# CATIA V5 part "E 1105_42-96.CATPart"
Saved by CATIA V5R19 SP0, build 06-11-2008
Definition: E 1105_42-96
Nomenclature: E 1105_42-96
Description: PART--DESC
Material "Brass": density 8216 kg/m3, Young's modulus 1.31e+11 Pa, Poisson ratio 0.35, thermal expansion 1.67e-05 1/K
Bounding box of the stored display mesh (mm): x 249.5 to 308.5, y 199.51 to 258.49, z -172 to -66
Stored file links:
  G:\UTB\Kombinované\Bakalářská práce\Catia\FORMA\E 1105_42-96.CATPart
  D:\Aplikace\CATIA\Nová složka\win_b64\startup\materials\Catalog.CATMaterial
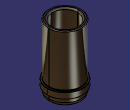
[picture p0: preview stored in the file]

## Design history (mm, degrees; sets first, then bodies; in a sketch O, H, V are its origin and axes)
Body1 "E 1105_42-96" (main body)
  Solid1: solid without history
